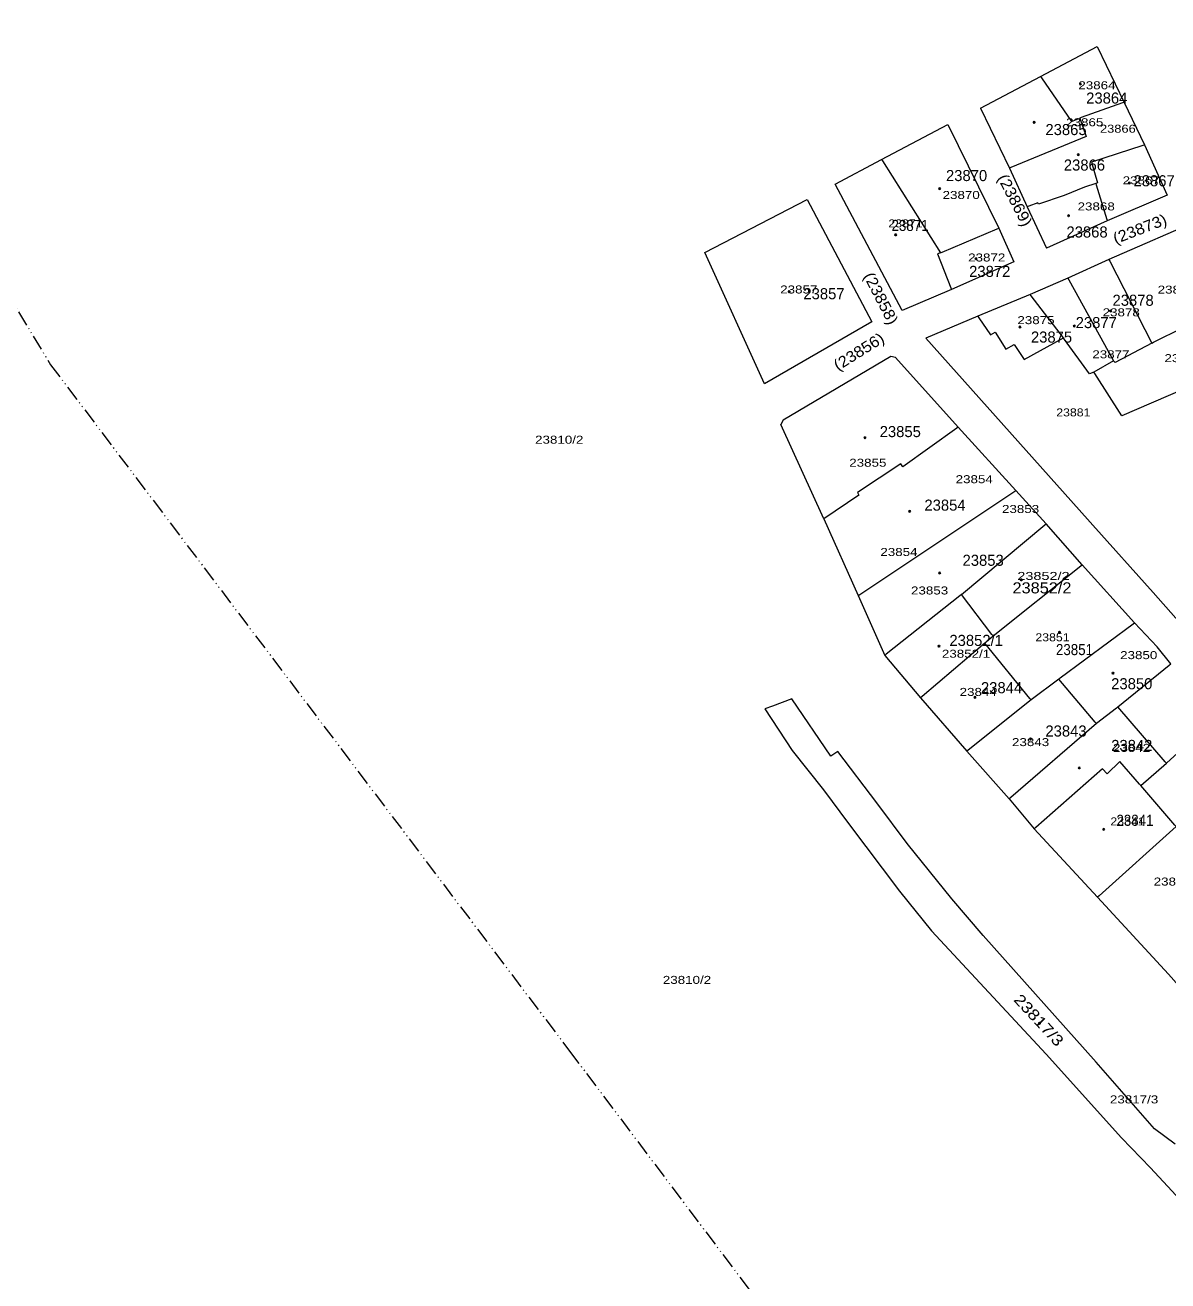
# Model space of a CAD drawing. Extents: x 649608 to 651081, y 237980 to 241202.
# Drawn here: x 650118.4 to 650489.8, y 238252.5 to 238660.5 of the extents above; entities that cross this region are included whole.
import ezdxf

# ---------------------------------------------------------------- set-up
doc = ezdxf.new("R2010")
doc.units = 0
doc.header["$PDMODE"] = 32
doc.header["$PDSIZE"] = 0.5
doc.linetypes.add('DASH_DOUBLE_DOT', pattern=[9.2, 5, -1.2, 0.3, -1.2, 0.3, -1.2])
for name, color, linetype in [('19', 7, 'Continuous'), ('20', 7, 'Continuous'), ('6', 7, 'Continuous')]:
    doc.layers.add(name, color=color, linetype=linetype)
for name, color, linetype, lineweight in [('3', 7, 'Continuous', 13), ('5', 7, 'Continuous', 13), ('52', 7, 'DASH_DOUBLE_DOT', 13)]:
    doc.layers.add(name, color=color, linetype=linetype, lineweight=lineweight)

msp = doc.modelspace()

# ---------------------------------------------------------------- linework, layer by layer
at = {"layer": '3'}
for p, q in [((650428.887, 238633.45), (650448.392, 238643.811)), ((650439.735, 238583.562), (650419.499, 238574.606)), ((650463.677, 238499.933), (650411.173, 238558.735)), ((650377.979, 238500.018), (650363.994, 238530.723))]:
    msp.add_line(p, q, dxfattribs=at)
for points in [[(650448.392, 238643.811), (650466.873, 238653.545), (650475.627, 238635.348), (650482.2, 238621.53)], [(650428.887, 238633.45), (650438.311, 238613.968), (650444.118, 238601.399), (650450.416, 238588.035)], [(650419.499, 238574.606), (650403.465, 238567.778), (650381.723, 238608.82), (650396.754, 238616.852), (650418.318, 238628.147)], [(650418.318, 238628.147), (650434.83, 238594.525), (650439.735, 238583.562)], [(650482.2, 238621.53), (650489.643, 238605.175), (650470.143, 238596.834), (650450.416, 238588.035)], [(650514.565, 238573.659), (650501.562, 238597.783), (650470.671, 238584.303), (650457.326, 238578.233), (650445.045, 238572.958), (650428.006, 238565.908), (650411.173, 238558.735)], [(650401.33, 238552.507), (650399.768, 238552.79), (650364.795, 238532.146), (650363.994, 238530.723)], [(650401.33, 238552.507), (650421.702, 238529.857), (650440.389, 238509.304)], [(650490.784, 238452.952), (650486.321, 238458.459), (650479, 238466.318), (650462.01, 238485.142), (650450.302, 238498.482), (650440.389, 238509.304)], [(650463.677, 238499.933), (650465.462, 238498.038), (650485.053, 238476.157), (650492.425, 238467.844), (650554.863, 238505.063)], [(650377.979, 238500.018), (650389.177, 238475.141), (650397.805, 238455.67), (650409.436, 238441.95), (650424.433, 238424.542), (650438.259, 238409.104), (650446.37, 238399.327), (650466.957, 238377.142), (650490.018, 238352.102), (650501.675, 238338.963)], [(650492.156, 238296.941), (650485.494, 238301.946), (650466.542, 238323.523), (650429.784, 238364.658), (650419.581, 238376.583), (650405.096, 238394.622), (650395.177, 238407.809), (650382.581, 238424.483), (650380.328, 238422.92), (650367.557, 238441.639), (650361.366, 238439.246), (650358.807, 238438.34), (650367.728, 238424.8), (650377.903, 238412.017), (650385.985, 238401.053), (650402.585, 238379.099), (650413.015, 238366.265), (650450.261, 238326.14), (650474.724, 238299.003), (650484.19, 238289.275), (650511.92, 238259.307)]]:
    msp.add_lwpolyline(points, dxfattribs=at)
msp.add_lwpolyline([(650372.63, 238603.811), (650393.557, 238564.014), (650358.73, 238543.951), (650339.354, 238586.593)], close=True, dxfattribs=at)
at = {"layer": '5'}
for points in [[(650448.392, 238643.811), (650448.737, 238643.311), (650458.501, 238629.18), (650461.172, 238630.248)], [(650475.627, 238635.348), (650475.127, 238635.172), (650461.672, 238630.424), (650461.172, 238630.248)], [(650461.172, 238630.248), (650463.284, 238624.295), (650438.811, 238614.175), (650438.311, 238613.968)], [(650482.2, 238621.53), (650481.7, 238621.368), (650464.99, 238615.967), (650466.963, 238609.243), (650466.378, 238609.024)], [(650396.754, 238616.852), (650397.07, 238616.352), (650415.937, 238586.493)], [(650466.378, 238609.024), (650462.689, 238607.766), (650456.093, 238605.082), (650447.775, 238602.251), (650447.581, 238602.764), (650444.618, 238601.596), (650444.118, 238601.399)], [(650466.378, 238609.024), (650466.532, 238608.524), (650469.989, 238597.334), (650470.143, 238596.834)], [(650415.937, 238586.493), (650416.437, 238586.706), (650434.33, 238594.312), (650434.83, 238594.525)], [(650415.937, 238586.493), (650414.996, 238586.103), (650419.303, 238575.106), (650419.499, 238574.606)], [(650470.671, 238584.303), (650470.928, 238583.803), (650484.63, 238557.158)], [(650457.326, 238578.233), (650457.601, 238577.733), (650472.099, 238551.417), (650465.778, 238547.739)], [(650484.63, 238557.158), (650485.13, 238557.408), (650504.385, 238567.04), (650503.968, 238567.761), (650514.065, 238573.381), (650514.565, 238573.659)], [(650455.889, 238558.816), (650445.428, 238572.458), (650445.045, 238572.958)], [(650428.006, 238565.908), (650428.346, 238565.408), (650432.139, 238559.83), (650433.739, 238560.708), (650437.176, 238555.151), (650439.841, 238556.748), (650443.066, 238551.819), (650455.889, 238558.816)], [(650465.778, 238547.739), (650464.354, 238547.141), (650456.252, 238558.316), (650455.889, 238558.816)], [(650484.63, 238557.158), (650472.641, 238550.903), (650472.599, 238550.943), (650472.099, 238551.417)], [(650525.879, 238552.125), (650525.379, 238551.97), (650514.498, 238548.602), (650494.718, 238542.098), (650474.912, 238533.525), (650466.099, 238547.239), (650465.778, 238547.739)], [(650421.702, 238529.857), (650421.202, 238529.5), (650403.683, 238516.993), (650402.981, 238517.968), (650388.984, 238508.66), (650389.432, 238507.806), (650377.979, 238500.018)], [(650389.177, 238475.141), (650389.677, 238475.475), (650440.389, 238509.304)], [(650422.727, 238475.465), (650449.802, 238498.065), (650450.302, 238498.482)], [(650432.987, 238462.031), (650461.51, 238484.744), (650462.01, 238485.142)], [(650422.727, 238475.465), (650422.227, 238475.068), (650398.305, 238456.067), (650397.805, 238455.67)], [(650432.987, 238462.031), (650432.605, 238462.531), (650422.727, 238475.465)], [(650454.363, 238448.016), (650454.863, 238448.387), (650478.5, 238465.947), (650479, 238466.318)], [(650430.29, 238459.634), (650409.936, 238442.374), (650409.436, 238441.95)], [(650430.29, 238459.634), (650430.79, 238460.078), (650432.987, 238462.031)], [(650445.394, 238441.222), (650444.984, 238441.722), (650430.29, 238459.634)], [(650473.575, 238438.984), (650490.284, 238452.546), (650490.784, 238452.952)], [(650466.662, 238433.563), (650466.237, 238434.063), (650454.363, 238448.016), (650445.394, 238441.222)], [(650445.394, 238441.222), (650424.933, 238424.94), (650424.433, 238424.542)], [(650473.575, 238438.984), (650473.075, 238438.592), (650466.662, 238433.563)], [(650489.338, 238420.666), (650488.908, 238421.166), (650473.575, 238438.984)], [(650489.338, 238420.666), (650506.179, 238435.923), (650506.679, 238436.376)], [(650466.662, 238433.563), (650438.759, 238409.535), (650438.259, 238409.104)], [(650481.066, 238413.404), (650480.627, 238413.904), (650474.23, 238421.186), (650470.106, 238417.252), (650468.6, 238418.844), (650446.87, 238399.766), (650446.37, 238399.327)], [(650492.493, 238400.089), (650492.064, 238400.589), (650481.066, 238413.404), (650489.338, 238420.666)], [(650492.493, 238400.089), (650467.457, 238377.591), (650466.957, 238377.142)]]:
    msp.add_lwpolyline(points, dxfattribs=at)
at = {"layer": '52'}
msp.add_lwpolyline([(649701.481, 241202.319), (649640.936, 240904.262), (649608.393, 240352.424), (649614.771, 240009.578), (649631.5, 239894.49), (649662.347, 239679.564), (649715.192, 239448.546), (649776.71, 239295.263), (649918.979, 238940.568), (649995.713, 238777.318), (650020.382, 238724.355), (650126.69, 238550.145), (650295.37, 238327.169), (650466.153, 238100.489), (650557.889, 237992.529), (650568.158, 237979.989)], dxfattribs=at)
at = {"layer": '6'}
for p in [(650461.409, 238641.362), (650446.374, 238628.889), (650460.698, 238618.373), (650415.662, 238607.32), (650477.31, 238609.182), (650457.545, 238598.529), (650401.362, 238592.315), (650427.442, 238584.565), (650366.749, 238573.881), (650471.22, 238567.603), (650441.775, 238562.388), (650459.405, 238562.687), (650391.413, 238526.404), (650405.908, 238502.499), (650415.664, 238482.487), (650442.17, 238480.256), (650454.605, 238463.182), (650415.413, 238458.707), (650472.013, 238449.94), (650427.141, 238442.088), (650445.167, 238428.56), (650461.016, 238419.155), (650468.992, 238399.164), (650448.094, 238336.172)]:
    msp.add_point(p, dxfattribs=at)

# ---------------------------------------------------------------- texts
at = {"layer": '19'}
for s, p in [('23864', (650463.276, 238634.968)), ('23865', (650450.024, 238624.729)), ('23866', (650456.009, 238613.211)), ('23870', (650417.703, 238609.789)), ('23867', (650478.667, 238608.091)), ('23868', (650456.864, 238591.454)), ('23872', (650425.227, 238578.655)), ('23857', (650371.361, 238571.403)), ('23878', (650471.827, 238569.27)), ('23877', (650459.856, 238562.018)), ('23875', (650445.32, 238557.325)), ('23855', (650396.157, 238526.608)), ('23854', (650410.692, 238502.718)), ('23853', (650423.09, 238484.801)), ('23852/1', (650418.815, 238458.778)), ('23844', (650429.074, 238443.419)), ('23850', (650471.398, 238444.699)), ('23843', (650450.022, 238429.341)), ('23842', (650471.398, 238424.648))]:
    msp.add_text(s, height=3.6, dxfattribs=at).set_placement(p)
for s, rotation, width, p in [('(23869)', 297.222, 1.1, (650434.351, 238610.869)), ('(23873)', 21.211, 1.1, (650472.848, 238589.275)), ('(23858)', 297.233, 1.1, (650390.802, 238578.982)), ('(23856)', 32.093, 1.1, (650382.604, 238548.025)), ('23817/3', 312.869, 1.2, (650439.468, 238343.645))]:
    msp.add_text(s, height=3.6, rotation=rotation, dxfattribs=dict(at, width=width)).set_placement(p)
for s, width, p in [('23871', 0.9, (650400.005, 238593.586)), ('23852/2', 1.1, (650439.334, 238475.842)), ('23851', 0.9, (650453.444, 238455.791)), ('23841', 0.9, (650473.108, 238400.332))]:
    msp.add_text(s, height=3.6, dxfattribs=dict(at, width=width)).set_placement(p)
at = {"layer": '20'}
for s, width, p in [('23864', 1.25, (650460.726, 238639.617)), ('23865', 1.25, (650456.761, 238627.601)), ('23866', 1.2, (650467.771, 238625.504)), ('23867', 1.25, (650475.127, 238608.729)), ('23870', 1.25, (650416.599, 238603.975)), ('23868', 1.25, (650460.484, 238600.261)), ('23871', 1.15, (650398.979, 238594.742)), ('23872', 1.25, (650424.905, 238583.666)), ('23857', 1.25, (650363.823, 238573.274)), ('23879', 1.25, (650486.505, 238573.23)), ('23875', 1.25, (650440.909, 238563.312)), ('23878', 1.25, (650468.615, 238565.848)), ('23877', 1.25, (650465.268, 238552.214)), ('23880', 1.25, (650488.712, 238550.975)), ('23881', 1.15, (650453.538, 238533.344)), ('23810/2', 1.25, (650284.157, 238524.471)), ('23855', 1.25, (650386.262, 238516.995)), ('23854', 1.25, (650420.847, 238511.644)), ('23853', 1.25, (650435.911, 238501.961)), ('23854', 1.25, (650396.376, 238487.993)), ('23852/2', 1.35, (650440.905, 238480.215)), ('23853', 1.25, (650406.334, 238475.495)), ('23851', 1.15, (650446.761, 238460.283)), ('23852/1', 1.25, (650416.378, 238454.944)), ('23850', 1.25, (650474.307, 238454.493)), ('23844', 1.25, (650422.139, 238442.54)), ('23843', 1.25, (650439.165, 238426.232)), ('23842', 1.25, (650471.986, 238424.368)), ('23841', 1.15, (650471.147, 238400.478)), ('23840', 1.25, (650485.214, 238380.93)), ('23810/2', 1.25, (650325.678, 238348.982)), ('23817/3', 1.25, (650470.983, 238310.156))]:
    msp.add_text(s, height=2.6, dxfattribs=dict(at, width=width)).set_placement(p)

doc.saveas('drawing.dxf')
